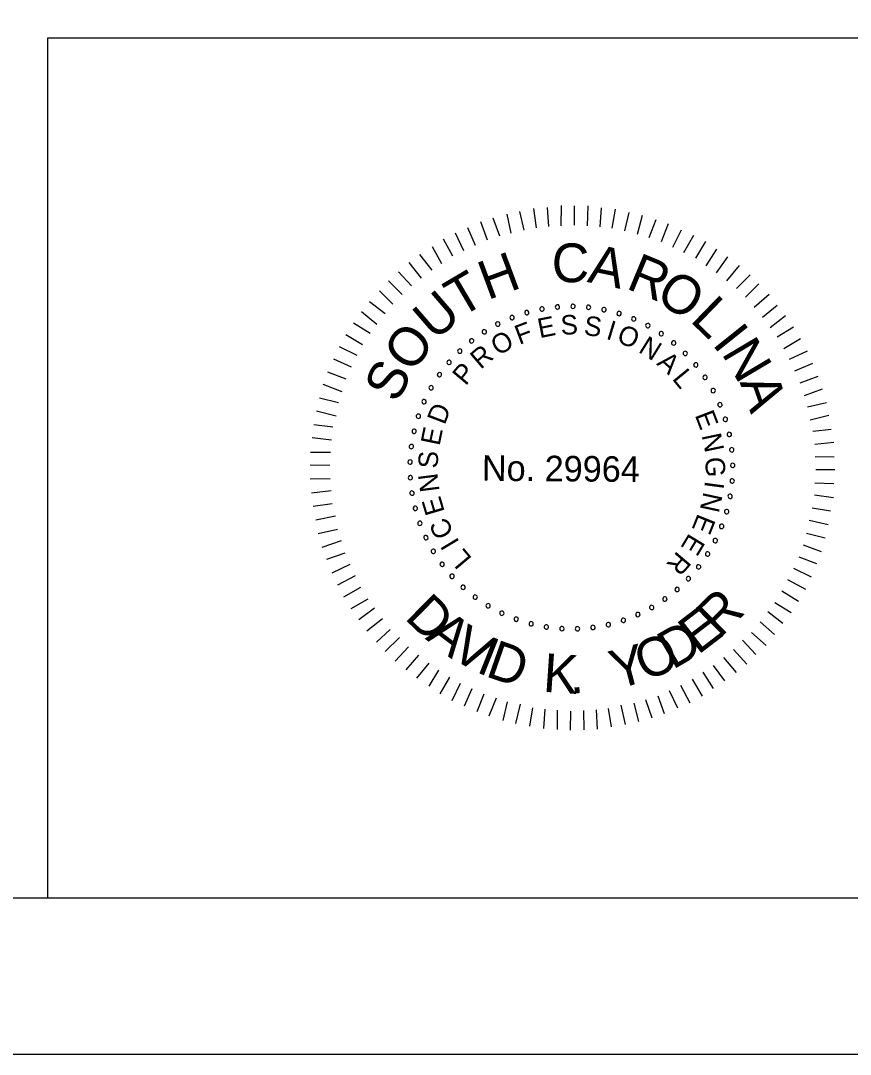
# Model space of a CAD drawing. Extents: x -149.6 to -53.3, y -21.7 to 37.
# Drawn here: x -89.48 to -82.41, y -21.66 to -12.85 of the extents above; entities that cross this region are included whole.
import ezdxf

# ---------------------------------------------------------------- set-up
doc = ezdxf.new("R2010")
doc.units = 0
for name, color, linetype in [('BR_BORDER LINES', 7, 'Continuous'), ('BR_TEXT', 7, 'Continuous'), ('Level 31', 7, 'Continuous')]:
    doc.layers.add(name, color=color, linetype=linetype)

msp = doc.modelspace()

# ---------------------------------------------------------------- linework, layer by layer
at = {"layer": 'BR_BORDER LINES'}
for p, q in [((-89.2486, -12.993), (-74.9414, -12.993)), ((-89.2486, -20.3265), (-89.2486, -12.993)), ((-144.7168, -20.3267), (-54.9406, -20.3267))]:
    msp.add_line(p, q, dxfattribs=at)
at = {"layer": 'BR_TEXT'}
for p, q in [((-85.0841, -14.6115), (-85.1079, -14.4489)), ((-84.9787, -14.6009), (-84.9888, -14.4384)), ((-84.8734, -14.5949), (-84.8719, -14.4233)), ((-84.7612, -14.5891), (-84.7599, -14.4243)), ((-84.6491, -14.5968), (-84.6431, -14.4252)), ((-84.5417, -14.6046), (-84.5289, -14.4422)), ((-85.3959, -14.6845), (-85.4542, -14.5307)), ((-85.2996, -14.6578), (-85.3348, -14.4951)), ((-85.1895, -14.6313), (-85.2272, -14.4731)), ((-84.4388, -14.6169), (-84.4099, -14.4547)), ((-84.3314, -14.6384), (-84.2935, -14.4808)), ((-84.2218, -14.6667), (-84.1792, -14.5047)), ((-85.6048, -14.7629), (-85.6677, -14.6136)), ((-85.5015, -14.718), (-85.5573, -14.5619)), ((-84.1236, -14.695), (-84.0651, -14.5422)), ((-84.0186, -14.7302), (-83.9601, -14.5751)), ((-83.9229, -14.7768), (-83.8485, -14.6286)), ((-85.7955, -14.8552), (-85.8767, -14.7103)), ((-85.7036, -14.8079), (-85.7733, -14.6585)), ((-83.8271, -14.8234), (-83.7435, -14.6753)), ((-85.8898, -14.9184), (-85.971, -14.7735)), ((-83.7268, -14.8723), (-83.641, -14.7288)), ((-83.6381, -14.937), (-83.5477, -14.7935)), ((-85.9727, -14.975), (-86.0769, -14.8391)), ((-83.5493, -14.995), (-83.4521, -14.8608)), ((-86.0625, -15.0428), (-86.169, -14.9092)), ((-83.463, -15.0643), (-83.3544, -14.9325)), ((-86.2285, -15.181), (-86.3464, -15.0634)), ((-86.1501, -15.1085), (-86.2612, -14.9886)), ((-83.3789, -15.1314), (-83.2635, -15.0134)), ((-86.3069, -15.2629), (-86.4228, -15.1497)), ((-83.304, -15.2052), (-83.1886, -15.0895)), ((-86.374, -15.347), (-86.5059, -15.2429)), ((-83.2291, -15.2883), (-83.1023, -15.1772)), ((-86.4434, -15.4356), (-86.5752, -15.3293)), ((-83.1566, -15.3735), (-83.0322, -15.2716)), ((-83.0932, -15.4633), (-82.9619, -15.3591)), ((-86.5012, -15.5129), (-86.6447, -15.4248)), ((-83.0344, -15.5416), (-82.8941, -15.4558)), ((-86.5662, -15.6108), (-86.7095, -15.525)), ((-82.9757, -15.6405), (-82.8331, -15.557)), ((-86.6127, -15.702), (-86.763, -15.6276)), ((-82.9284, -15.7324), (-82.7745, -15.6605)), ((-86.6593, -15.8), (-86.812, -15.7323)), ((-82.8812, -15.8312), (-82.7296, -15.7661)), ((-86.7059, -15.9026), (-86.8609, -15.8441)), ((-86.7388, -16.0099), (-86.903, -15.9491)), ((-82.8363, -15.9346), (-82.6847, -15.8786)), ((-82.8006, -16.0424), (-82.6467, -15.9842)), ((-86.7716, -16.1057), (-86.9338, -16.0655)), ((-82.7738, -16.1387), (-82.6134, -16.1012)), ((-86.7908, -16.2177), (-86.9575, -16.1752)), ((-82.7519, -16.2511), (-82.5913, -16.2112)), ((-86.8191, -16.3136), (-86.9814, -16.2917)), ((-82.7298, -16.3474), (-82.5718, -16.3281)), ((-86.8314, -16.4233), (-86.996, -16.4037)), ((-82.7124, -16.4573), (-82.5498, -16.4404)), ((-86.8392, -16.5286), (-87.0108, -16.5271)), ((-82.7087, -16.5627), (-82.5485, -16.564)), ((-86.8447, -16.6383), (-87.0117, -16.6369)), ((-82.7027, -16.6725), (-82.5403, -16.6738)), ((-86.841, -16.7528), (-87.0127, -16.756)), ((-82.7106, -16.7869), (-82.5504, -16.7928)), ((-86.835, -16.8559), (-86.9999, -16.875)), ((-82.716, -16.8899), (-82.5536, -16.9118)), ((-86.8244, -16.9657), (-86.9872, -16.9896)), ((-82.7352, -16.9995), (-82.5775, -17.026)), ((-86.7979, -17.0713), (-86.9652, -17.1065)), ((-86.7805, -17.1836), (-86.9433, -17.2211)), ((-82.759, -17.1046), (-82.599, -17.1425)), ((-82.7827, -17.2166), (-82.6229, -17.2568)), ((-86.7493, -17.2821), (-86.9145, -17.338)), ((-82.8111, -17.3147), (-82.6582, -17.3732)), ((-86.7181, -17.3854), (-86.8741, -17.4414)), ((-82.8485, -17.4174), (-82.6979, -17.4759)), ((-86.6732, -17.4842), (-86.827, -17.5561)), ((-82.8951, -17.5154), (-82.7446, -17.5898)), ((-86.6282, -17.5807), (-86.7798, -17.6595)), ((-82.9439, -17.6111), (-82.7912, -17.6925)), ((-86.5832, -17.6795), (-86.728, -17.763)), ((-82.9928, -17.7092), (-82.8516, -17.795)), ((-86.5199, -17.7784), (-86.6648, -17.8619)), ((-86.4633, -17.8567), (-86.5969, -17.954)), ((-83.1132, -17.8844), (-82.9836, -17.9838)), ((-83.0532, -17.8071), (-82.9143, -17.8929)), ((-86.3955, -17.9465), (-86.5291, -18.0507)), ((-83.1781, -17.9731), (-83.0554, -18.0794)), ((-86.3298, -18.0363), (-86.4475, -18.1452)), ((-83.252, -18.0617), (-83.1271, -18.1726)), ((-86.2526, -18.1056), (-86.3726, -18.2259)), ((-83.3281, -18.1298), (-83.2147, -18.252)), ((-86.1755, -18.1863), (-86.2886, -18.3089)), ((-83.4043, -18.2092), (-83.2909, -18.3337)), ((-86.089, -18.2556), (-86.1976, -18.3807)), ((-86.0003, -18.3251), (-86.1067, -18.4523)), ((-83.4895, -18.2771), (-83.3831, -18.4039)), ((-85.9185, -18.383), (-86.002, -18.5218)), ((-83.6667, -18.4016), (-83.5786, -18.5418)), ((-83.577, -18.3451), (-83.4819, -18.474)), ((-85.8251, -18.4432), (-85.9087, -18.5867)), ((-85.734, -18.4966), (-85.8063, -18.6448)), ((-83.7564, -18.4603), (-83.673, -18.6052)), ((-85.636, -18.5432), (-85.7013, -18.6914)), ((-85.5335, -18.5898), (-85.5918, -18.7404)), ((-83.9541, -18.5571), (-83.8821, -18.7064)), ((-83.8576, -18.5121), (-83.7765, -18.6616)), ((-85.4284, -18.6227), (-85.4893, -18.7778)), ((-85.3326, -18.6556), (-85.3705, -18.8131)), ((-85.2229, -18.6747), (-85.2632, -18.8392)), ((-84.3648, -18.6818), (-84.3295, -18.8469)), ((-84.2548, -18.6645), (-84.2148, -18.8227)), ((-84.1562, -18.6332), (-84.1002, -18.7893)), ((-84.0506, -18.602), (-83.9946, -18.7536)), ((-85.1179, -18.7054), (-85.1443, -18.8607)), ((-85.0127, -18.7176), (-85.0255, -18.8824)), ((-84.9075, -18.7254), (-84.9088, -18.8902)), ((-84.7955, -18.7332), (-84.7968, -18.8957)), ((-84.6832, -18.7272), (-84.68, -18.8921)), ((-84.5757, -18.7213), (-84.5656, -18.8862)), ((-84.4726, -18.7107), (-84.4464, -18.8665))]:
    msp.add_line(p, q, dxfattribs=at)
for centre, start, end in [((-85.1665, -15.3356), 16.14222, 196.14222), ((-85.1665, -15.3356), 196.14222, 16.14222), ((-85.0371, -15.3051), 10.60376, 190.60376), ((-85.0371, -15.3051), 190.60376, 10.60376), ((-84.9054, -15.2873), 5.06529, 185.06529), ((-84.9054, -15.2873), 185.06529, 5.06529), ((-84.7727, -15.2822), 359.52683, 179.52683), ((-84.7727, -15.2822), 179.52683, 359.52683), ((-84.64, -15.29), 173.98837, 353.98837), ((-84.64, -15.29), 353.98837, 173.98837), ((-84.5087, -15.3105), 168.44991, 348.44991), ((-84.5087, -15.3105), 348.44991, 168.44991), ((-84.38, -15.3437), 342.91145, 162.91145), ((-85.4133, -15.4332), 27.21914, 207.21914), ((-85.2923, -15.3784), 21.68068, 201.68068), ((-85.2923, -15.3784), 201.68068, 21.68068), ((-84.38, -15.3437), 162.91145, 342.91145), ((-84.2551, -15.389), 157.37299, 337.37299), ((-84.2551, -15.389), 337.37299, 157.37299), ((-85.5286, -15.4994), 32.7576, 212.7576), ((-85.5286, -15.4994), 212.7576, 32.7576), ((-85.4133, -15.4332), 207.21914, 27.21914), ((-84.1352, -15.4463), 151.83453, 331.83453), ((-84.1352, -15.4463), 331.83453, 151.83453), ((-84.0214, -15.5148), 146.29606, 326.29606), ((-84.0214, -15.5148), 326.29606, 146.29606), ((-85.6369, -15.5764), 38.29606, 218.29606), ((-85.6369, -15.5764), 218.29606, 38.29606), ((-83.9147, -15.594), 140.7576, 320.7576), ((-83.9147, -15.594), 320.7576, 140.7576), ((-85.7372, -15.6635), 43.83453, 223.83453), ((-85.7372, -15.6635), 223.83453, 43.83453), ((-83.8161, -15.6831), 135.21914, 315.21914), ((-83.8161, -15.6831), 315.21914, 135.21914), ((-85.8287, -15.7598), 49.37299, 229.37299), ((-85.8287, -15.7598), 229.37299, 49.37299), ((-83.7266, -15.7814), 129.68068, 309.68068), ((-83.7266, -15.7814), 309.68068, 129.68068), ((-85.9105, -15.8646), 54.91145, 234.91145), ((-85.9105, -15.8646), 234.91145, 54.91145), ((-83.647, -15.8878), 124.14222, 304.14222), ((-83.647, -15.8878), 304.14222, 124.14222), ((-85.9817, -15.9767), 60.44991, 240.44991), ((-85.9817, -15.9767), 240.44991, 60.44991), ((-83.5781, -16.0014), 118.60376, 298.60376), ((-83.5781, -16.0014), 298.60376, 118.60376), ((-86.0418, -16.0952), 65.98837, 245.98837), ((-86.0418, -16.0952), 245.98837, 65.98837), ((-83.5204, -16.1211), 113.06529, 293.06529), ((-83.5204, -16.1211), 293.06529, 113.06529), ((-86.0902, -16.219), 71.52683, 251.52683), ((-86.0902, -16.219), 251.52683, 71.52683), ((-83.4746, -16.2458), 107.52683, 287.52683), ((-83.4746, -16.2458), 287.52683, 107.52683), ((-86.1264, -16.3469), 77.06529, 257.06529), ((-86.1264, -16.3469), 257.06529, 77.06529), ((-83.441, -16.3744), 101.98837, 281.98837), ((-83.441, -16.3744), 281.98837, 101.98837), ((-86.1502, -16.4776), 82.60376, 262.60376), ((-86.1502, -16.4776), 262.60376, 82.60376), ((-83.4199, -16.5056), 96.44991, 276.44991), ((-83.4199, -16.5056), 276.44991, 96.44991), ((-86.1611, -16.61), 88.14222, 268.14222), ((-86.1611, -16.61), 268.14222, 88.14222), ((-83.4117, -16.6382), 90.91145, 270.91145), ((-83.4117, -16.6382), 270.91145, 90.91145), ((-86.1593, -16.7429), 93.68068, 273.68068), ((-86.1593, -16.7429), 273.68068, 93.68068), ((-83.4162, -16.771), 85.37299, 265.37299), ((-83.4162, -16.771), 265.37299, 85.37299), ((-86.1446, -16.875), 99.21914, 279.21914), ((-86.1446, -16.875), 279.21914, 99.21914), ((-83.4336, -16.9027), 79.83453, 259.83453), ((-83.4336, -16.9027), 259.83453, 79.83453), ((-86.1173, -17.005), 104.7576, 284.7576), ((-86.1173, -17.005), 284.7576, 104.7576), ((-83.4636, -17.0322), 74.29606, 254.29606), ((-83.4636, -17.0322), 254.29606, 74.29606), ((-86.0775, -17.1318), 110.29606, 290.29606), ((-86.0775, -17.1318), 290.29606, 110.29606), ((-83.506, -17.1581), 68.7576, 248.7576), ((-83.506, -17.1581), 248.7576, 68.7576), ((-86.0257, -17.2542), 115.83453, 295.83453), ((-86.0257, -17.2542), 295.83453, 115.83453), ((-83.5603, -17.2794), 63.21914, 243.21914), ((-83.5603, -17.2794), 243.21914, 63.21914), ((-85.9623, -17.371), 121.37299, 301.37299), ((-85.9623, -17.371), 301.37299, 121.37299), ((-83.626, -17.3949), 57.68068, 237.68068), ((-83.626, -17.3949), 237.68068, 57.68068), ((-85.8879, -17.4811), 126.91145, 306.91145), ((-85.8879, -17.4811), 306.91145, 126.91145), ((-83.7026, -17.5035), 52.14222, 232.14222), ((-83.7026, -17.5035), 232.14222, 52.14222), ((-85.8033, -17.5835), 132.44991, 312.44991), ((-85.8033, -17.5835), 312.44991, 132.44991), ((-83.7894, -17.6041), 46.60376, 226.60376), ((-83.7894, -17.6041), 226.60376, 46.60376), ((-85.7092, -17.6773), 137.98837, 317.98837), ((-85.7092, -17.6773), 317.98837, 137.98837), ((-83.8854, -17.696), 41.06529, 221.06529), ((-83.8854, -17.696), 221.06529, 41.06529), ((-85.6064, -17.7616), 143.52683, 323.52683), ((-85.6064, -17.7616), 323.52683, 143.52683), ((-83.9899, -17.7781), 35.52683, 215.52683), ((-83.9899, -17.7781), 215.52683, 35.52683), ((-85.496, -17.8355), 149.06529, 329.06529), ((-85.496, -17.8355), 329.06529, 149.06529), ((-85.379, -17.8985), 154.60376, 334.60376), ((-85.379, -17.8985), 334.60376, 154.60376), ((-84.1017, -17.8498), 29.98837, 209.98837), ((-84.1017, -17.8498), 209.98837, 29.98837), ((-85.2565, -17.9498), 160.14222, 340.14222), ((-85.2565, -17.9498), 340.14222, 160.14222), ((-85.1295, -17.9891), 345.68068, 165.68068), ((-84.4713, -17.9959), 13.37299, 193.37299), ((-84.3436, -17.9592), 18.91145, 198.91145), ((-84.3436, -17.9592), 198.91145, 18.91145), ((-84.22, -17.9104), 24.44991, 204.44991), ((-84.22, -17.9104), 204.44991, 24.44991), ((-85.1295, -17.9891), 165.68068, 345.68068), ((-84.9994, -18.016), 171.21914, 351.21914), ((-84.9994, -18.016), 351.21914, 171.21914), ((-84.8673, -18.0302), 356.7576, 176.7576), ((-84.8673, -18.0302), 176.7576, 356.7576), ((-84.7344, -18.0316), 2.29606, 182.29606), ((-84.7344, -18.0316), 182.29606, 2.29606), ((-84.602, -18.0201), 7.83453, 187.83453), ((-84.602, -18.0201), 187.83453, 7.83453), ((-84.4713, -17.9959), 193.37299, 13.37299)]:
    msp.add_arc(centre, 0.0187, start, end, dxfattribs=at)
at = {"layer": 'Level 31'}
msp.add_lwpolyline([(-149.6056, -21.6598), (-53.6056, -21.6598), (-53.6056, 37.0068), (-149.6056, 37.0068)], close=True, dxfattribs=at)

# ---------------------------------------------------------------- texts
at = {"layer": 'BR_TEXT'}
for s, height, rotation, p in [('C', 0.3309, 359.54822, (-84.9552, -15.0753)), ('A', 0.3309, 348.19813, (-84.6581, -15.0732)), ('H', 0.3309, 20.36371, (-85.5004, -15.2308)), ('R', 0.3309, 337.43439, (-84.3295, -15.1262)), ('T', 0.3309, 30.49921, (-85.7348, -15.3842)), ('O', 0.3305, 326.58689, (-84.0835, -15.2242)), ('U', 0.3309, 40.80225, (-85.9512, -15.5836)), ('L', 0.3309, 315.94879, (-83.7833, -15.4049)), ('F', 0.166, 20.61271, (-85.2304, -15.6118)), ('E', 0.166, 11.41035, (-85.0565, -15.554)), ('S', 0.166, 2.20798, (-84.8757, -15.5247)), ('S', 0.166, 352.66081, (-84.6857, -15.5253)), ('I', 0.166, 343.11363, (-84.4984, -15.5573)), ('O', 0.3309, 52.0267, (-86.1501, -15.8607)), ('O', 0.166, 30.84774, (-85.41, -15.7079)), ('O', 0.166, 338.43918, (-84.4092, -15.5843)), ('I', 0.3309, 308.66128, (-83.593, -15.603)), ('N', 0.166, 328.20415, (-84.2235, -15.6681)), ('N', 0.3308, 300.70365, (-83.5114, -15.6814)), ('R', 0.166, 40.39491, (-85.5597, -15.8249)), ('S', 0.3305, 63.25114, (-86.271, -16.1157)), ('P', 0.166, 49.94209, (-85.6879, -15.9652)), ('A', 0.166, 318.65698, (-84.0663, -15.7748)), ('L', 0.166, 309.45461, (-83.9335, -15.901)), ('A', 0.3309, 289.47921, (-83.3535, -15.9295)), ('D', 0.166, 69.03644, (-85.8664, -16.2992)), ('E', 0.166, 291.049, (-83.7365, -16.2085)), ('E', 0.166, 78.23881, (-85.9107, -16.477)), ('N', 0.166, 281.84664, (-83.6773, -16.3819)), ('S', 0.166, 87.78598, (-85.9259, -16.6664)), ('No. 29964', 0.21799, 359.52683, (-85.5496, -16.7688)), ('G', 0.166, 272.29946, (-83.6461, -16.5694)), ('N', 0.166, 97.33316, (-85.9095, -16.8558)), ('I', 0.166, 262.40836, (-83.6469, -16.7662)), ('E', 0.166, 106.53552, (-85.8641, -17.0333)), ('N', 0.166, 257.73391, (-83.6592, -16.8586)), ('C', 0.166, 116.42662, (-85.7844, -17.2133)), ('E', 0.166, 248.18673, (-83.7072, -17.0424)), ('I', 0.166, 121.10107, (-85.7362, -17.293)), ('E', 0.166, 238.98437, (-83.7818, -17.2097)), ('L', 0.166, 129.95951, (-85.6278, -17.4321)), ('R', 0.166, 229.78201, (-83.8821, -17.363)), ('D', 0.3295, 315.40526, (-86.2158, -17.9404)), ('R', 0.3295, 44.59474, (-83.5202, -18.1152)), ('E', 0.3295, 37.53391, (-83.7085, -18.259)), ('A', 0.3295, 322.83772, (-86.0382, -18.1154)), ('V', 0.3295, 330.51792, (-85.8325, -18.2706)), ('D', 0.3295, 30.10145, (-83.9242, -18.384)), ('I', 0.3295, 338.19813, (-85.6079, -18.3969)), ('D', 0.3295, 340.79949, (-85.5282, -18.4328)), ('O', 0.3295, 22.42125, (-84.1622, -18.4829)), ('K', 0.3295, 356.09796, (-85.0342, -18.5676)), ('Y', 0.3295, 14.86491, (-84.4072, -18.5482)), ('.', 0.3295, 3.15879, (-84.7978, -18.5844))]:
    msp.add_text(s, height=height, rotation=rotation, dxfattribs=at).set_placement(p)

doc.saveas('drawing.dxf')
